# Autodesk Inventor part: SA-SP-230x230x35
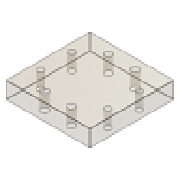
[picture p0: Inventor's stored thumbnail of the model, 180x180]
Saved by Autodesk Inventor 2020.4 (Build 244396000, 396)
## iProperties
Created: 2019-01
Part Number: SA-SP-230x230x35
Material: S 55 C
Description: Support Plate
Document SubType Name: Modeling
Designer: mel
Standard Revision: 1
Manufacturer: FUTABA
Language: fr-FR
Size Designation: 230x230x35
Categories: <MemberInstance><Categories><Category DisplayName="Moule" InternalName="349578f2-f4d4-4954-8c09-8e99297a61c0" Mnemonic="MOLD"><Category DisplayName="Plaque de m
Density: 7.85 g/cm^3
Appearance: Polycarbonate - Smoked
IsCustomPart: 1
Author: mel
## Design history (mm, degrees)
sketch "Sketch1"
  geometry: L1 (-115, 115)-(115, 115); L2 (115, 115)-(115, -115); L3 (115, -115)-(-115, -115); L4 (-115, -115)-(-115, 115); 5 further points
  constraints: 8 end point, 2 midpoint, 2 parallel, 1 horizontal, 1 horizontal alignment, 1 perpendicular, 1 vertical alignment
  dimensions: "d68" = 230 distance between parallel lines of L2 L4 (= W_); "d69" = 230 distance between parallel lines of L3 L1 (= L); "d70" = 90 vertical distance of point (0, 0) point (-53, 90) (= 0.5 x RP_L); "d71" = 53 horizontal distance of point (0, 0) point (-53, 90) (= 0.5 x RP_W); "d72" = 53 vertical distance of point (0, 0) point (-92.5, 53) (= 0.5 x S1_L); "d73" = 92.5 horizontal distance of point (0, 0) point (-92.5, 53) (= 0.5 x S1_W)
extrude "Extrusion1" new body sketch "Sketch1" distance "d20" = 35 (= H_); taper "d30" = 0 deg
hole "Hole1" sketch "Sketch1" diameter "d74" = 14 (= S1_d1); stored, may be unused: countersink angle "d78" = 90 deg, drill point angle "d80" = 0 deg; dims "d75" = 6, "d76" = 4, "d77" = 2, "d79" = 35 (= H_)
pattern_linear "Rectangular Pattern1" dims "d102" = 106 (computed from S1_L, Ns), "d105" = 185 (computed from S1_W, Nw)
hole "Hole2" sketch "Sketch1" diameter "d81" = 16 (= RP_d1); stored, may be unused: countersink angle "d85" = 90 deg, drill point angle "d87" = 0 deg; dims "d82" = 6, "d83" = 4, "d84" = 2, "d86" = 35 (= H_)
pattern_linear "Rectangular Pattern2" dims "d108" = 180 (computed from RP_L, Nl), "d111" = 106 (computed from RP_W, Nw)
chamfer "Chamfer1" distance "d112" = 0.5; stored, may be unused: second distance "d113" = 2, angle "d114" = 45 deg
body "Solid1"
other parameters: "L" = 230 [user parameter; used in 1 equation term], "W_" = 230 [user parameter; used in 1 equation term], "H_" = 35 [user parameter; used in 3 equation terms], "RP_W" = 106 [user parameter; used in 2 equation terms], "S1_d1" = 14 [user parameter; used in 1 equation term], "RP_d1" = 16 [user parameter; used in 1 equation term], "S1_L" = 106 [user parameter; used in 2 equation terms], "S1_W" = 185 [user parameter; used in 2 equation terms]
